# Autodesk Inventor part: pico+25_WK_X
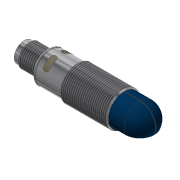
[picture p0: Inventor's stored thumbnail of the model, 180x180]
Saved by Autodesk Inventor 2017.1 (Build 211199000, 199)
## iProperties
Shininess: 20.0
Length Units: 11269
Angle Units: 11279
Time Units: 11290
Mass Units: 11283
Length Display Precision: 2
Angle Display Precision: 2
Part Number: pico+25_WK_X
Material: Nichtrostender Stahl - 440C
Document SubType Name: Modellieren
Description: Ipc-25 /CXX/M18
Checked By: Alves
Created: 2005-08
Designer: Ohle
Manufacturer: Standard
Standards Organization: Custom
Appearance: Aluminium - poliert
Density: 0.0
Volumn: 0.0
Area: 0.0
PropertySet Name: Model Information
Control State: 0
Master: False
Checked Out: False
BESTELLNUMMER: Ipc-25 /CXX/M18
ME: ST
Title: Ipc Sensoren
Author: Ohle
Comments: keine Bemerkung
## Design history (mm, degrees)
sketch "Skizze10"
  geometry: L1 (-43.018, 0)-(17.482, 0); L2 (-39.018, 6.5)-(-39.018, 7.25); L3 (-45.9, 8)-(-45.9, 8); L4 (-23.268, 9)-(0.232, 9); L5 (1.482, 0)-(-82.2, 0); L6 (-24.018, 8.25)-(-23.268, 9); L7 (0.982, 8.25)-(0.232, 9); L8 (-50.518, 6)-(-39.518, 6); L9 (-37.418, 8.25)-(-24.018, 8.25); L10 (-51.018, 4.5)-(-43.018, 4.5); L11 (-43.018, 0)-(-43.018, 4.5); L12 (-37.518, 8.25)-(-38.018, 8.25); L13 (-39.518, 6)-(-39.018, 6.5); L14 (-51.018, 5.5)-(-51.018, 4.5); L15 (-51.018, 5.5)-(-50.518, 6); L16 (-37.518, 8.25)-(-37.518, 8.15); L17 (-37.518, 8.15)-(-37.418, 8.15); L18 (-37.418, 8.15)-(-37.418, 8.25); L19 (0.982, 8.25)-(9.232, 8.25); L20 (17.482, 0)-(17.482, 0); A1 r 1 centre (-38.018, 7.25) between (-38.018, 8.25) and (-39.018, 7.25); A2 r 8.25 centre (9.232, 0) between (17.482, 0) and (9.232, 8.25); 4 further points
  constraints: 41 end point, 8 point on line, 5 parallel, 4 perpendicular, 4 point on circle, 4 tangent, 2 centre point, 2 horizontal, 1 collinear
  dimensions: "d171" = 4.5 distance between parallel lines of L10 L1; "d250" = 0.75 distance from line of L7.start L4; "d256" = 45 deg angle of L4 L6; "d257" = 8.25 distance between parallel lines of L5 L9; "d263" = 8.25 distance between parallel lines of L5 L12; "d266" = 12 distance from line of L2 L14.start; "d269" = 6 distance between parallel lines of L5 L8; "d289" = 135 deg angle of L7 L4; "d290" = 0.5 horizontal distance of L8.end L2.start; "d291" = 45 deg angle of L13 L8 (derived); "d293" = 0.5 horizontal distance of L14.start L8.start; "d294" = 45 deg angle of L15 L8 (derived); "d295" = 8 distance of L10.start L10.end; "d296" = 1.5 distance of L12.start point (-39.018, 8.25); "d297" = 0.1 distance of L16.end L17.end; "d298" = 8.15 distance between parallel lines of L17 L1; "d299" = 15 distance from line of L6.start L2; "d300" = 1 radius of A1; "d338" = 8.25 radius of A2; "d339" = 16.5 horizontal distance of L20.end L7.start; "d340" = 8.25 distance between parallel lines of L1 L19 (derived); "d365" = 25 distance of L7.start L6.start
revolve "Grundkörper pico+" sketch "Skizze10" stored, may be unused: angle "d168" = 90 deg
feature "Gewinde M12" dims "d174" = 10, "d175" = 0
feature "Gewinde M 18" dims "d179" = 10, "d180" = 0
workplane "Arbeitsebene1"
workplane "Arbeitsebene2"
sketch "Skizze13"
  geometry: L1 (-3.409, -3.409)-(3.61, 3.61); L2 (-3.439, 3.439)-(4.105, -4.105); L3 (-12.6, 0)-(12.6, 0) reference; C1 r 0.5 at (2.121, -2.121); C2 r 0.5 at (2.121, 2.121); C3 r 0.5 at (-2.121, 2.121); C4 r 0.5 at (-2.121, -2.121); C5 r 4.5 at (0, 0) reference; C6 r 0.5 at (0, 0); A1 r 3 centre (0, 0) between (-2.121, 2.121) and (2.121, 2.121); 2 further points
  constraints: 6 centre point, 6 point on line, 4 coincident, 4 end point, 4 equal radius, 4 point on circle, 1 horizontal alignment, 1 perpendicular
  dimensions: "d208" = 1 diameter of C3; "d209" = 6 diameter of A1
extrude "Pole" join sketch "Skizze13" distance "d212" = 7; taper "d213" = 0 deg
fillet "Rundung Pole" dims "d214" = 0.5
sketch "Skizze14"
  geometry: C1 r 0.5 at (0, -4.5); A1 r 4.5 centre (0, 0) between (4.435, -0.762) and (4.435, 0.762); A2 r 4.5 centre (0, 0) between (0, 4.5) and (0.499, 4.472) reference; A3 r 0.5 centre (0, 4.5) between (-0.499, 4.472) and (0.499, 4.472); 3 further points
  constraints: 9 point on circle, 3 centre point, 3 coincident, 1 horizontal alignment, 1 vertical alignment
  dimensions: "d215" = 9 diameter of A1; "d280" = 1 diameter of A3; "d330" = 1 diameter of C1
extrude "Verdrehsicherung" join sketch "Skizze14" distance "d217" = 7; taper "d218" = 0 deg
sketch "Skizze18"
  geometry: C1 r 7.25 at (0, 0) reference; C2 r 1 at (-8.15, 0)
  constraints: 1 centre point, 1 horizontal alignment
  dimensions: "d328" = 2 diameter of C2; "d329" = 8.15 distance of C1.centre C2.centre
extrude "Bohrung Ausrichtung" cut sketch "Skizze18" distance "d316" = 0.75; taper "d317" = 0 deg
workplane "Arbeitsebene4"
sketch "Skizze19"
  geometry: L1 (-39.018, 0)-(-30.18, 0); L2 (-34.718, -7.5)-(-34.718, -3); L3 (-31.718, -7.5)-(-31.718, -3); L4 (-31.718, 3)-(-31.718, 7.5); L5 (-34.718, 3)-(-34.718, 7.5); A1 r 1.5 centre (-33.218, 3) between (-31.718, 3) and (-34.718, 3); A2 r 1.5 centre (-33.218, -3) between (-34.718, -3) and (-31.718, -3); A3 r 1.5 centre (-33.218, 7.5) between (-31.718, 7.5) and (-34.718, 7.5); A4 r 1.5 centre (-33.218, -7.5) between (-34.718, -7.5) and (-31.718, -7.5); 4 further points; 1 other entity
  constraints: 10 end point, 8 point on circle, 8 tangent, 4 centre point, 3 equal radius, 2 vertical alignment, 1 horizontal, 2 other
  dimensions: "d319" = 3 diameter of A2; "d320" = 6 distance of A2.centre A1.centre; "d321" = 4.5 distance of A1.centre A3.centre; "d322" = 4.5 distance of A4.centre A2.centre; "d323" = 3 distance from line of A2.centre L1; "d324" = 5.8 dimension on A1.centre; "d325" = 5.8 dimension on A2.centre
feature "Prägen LED-Fenster" sketch "Skizze19" dims "d326" = 0.01, "d327" = 0
workplane "Arbeitsebene5"
sketch "Skizze20"
  geometry: L1 (9.232, -8.25)-(9.232, 8.25) reference; L2 (0.982, -8.25)-(0.982, 8.25) reference; L3 (9.232, -8.25)-(9.232, 8.25) reference; L4 (1.482, -8.25)-(18.508, -8.25); L5 (18.508, -8.25)-(18.508, 8.25); L6 (18.508, 8.25)-(1.482, 8.25); L7 (1.482, 8.25)-(1.482, -8.25)
  constraints: 8 end point, 2 parallel, 1 horizontal, 1 perpendicular
  dimensions: "d342" = 0.5 distance between parallel lines of L7 L2
extrude "USW-Fläche Winkelkopf" cut sketch "Skizze20" distance "d343" = 4.8; taper "d344" = 0 deg
sketch "Skizze21"
  geometry: C1 r 7 at (-9.232, 0); A1 r 7.494 centre (-9.232, 0) between (-9.232, 7.494) and (-9.232, -7.494) reference
  constraints: 1 centre point, 1 coincident
  dimensions: "d345" = 14 diameter of C1
extrude "Extrusion6" cut sketch "Skizze21" distance "d346" = 0.01; taper "d347" = 0 deg
sketch "Skizze22"
  geometry: C1 r 7 at (0, 0) reference; C2 r 4 at (0, 0)
  constraints: 1 centre point, 1 coincident
  dimensions: "d348" = 8 diameter of C2
extrude "Extrusion7" join sketch "Skizze22" distance "d349" = 0.01; taper "d350" = 0 deg
sketch "Skizze28"
  geometry: L1 (-0.982, 8.25)-(-9.232, 8.25) reference; L2 (-0.982, 8.25)-(-0.982, -8.25) reference; L3 (-9.232, -3.45)-(-16.726, -3.45) reference; L4 (-9.232, 8.15)-(-0.982, 8.15); A1 r 8.25 centre (-9.232, 0) between (-9.232, 8.25) and (-16.726, -3.45) reference; A2 r 8.15 centre (-9.232, 0) between (-9.232, 8.15) and (-16.616, -3.45)
  constraints: 2 end point, 2 point on circle, 2 point on line, 1 centre point, 1 coincident, 1 perpendicular, 1 tangent
  dimensions: "d362" = 0.1 radial gap between concentric circles of A2 A1
extrude "Extrusion8" cut sketch "Skizze28" stored distance "d363" = 0.3; taper "d364" = 0 deg
feature "Verdickung1" dims "d366" = 0.1, "d367" = 0.1
sketch "Skizze29"
  geometry: C1 r 5.5 at (0, 0); C2 r 4.5 at (0, 0); C3 r 4.15 at (0, 0); C4 r 5.25 at (0, 0); 2 further points
  constraints: 4 centre point
  dimensions: "d368" = 8.3 diameter of C3; "d369" = 10.5 diameter of C4
extrude "Extrusion9" join sketch "Skizze29" stored distance "d370" = 1; taper "d371" = 0 deg
sketch "Skizze30"
  geometry: C1 r 5.25 at (0, 0) reference; C2 r 7.996 at (0, 0); 1 further point
  constraints: 1 centre point
extrude "Extrusion10" cut sketch "Skizze30" distance "d372" = 2.5; taper "d373" = 0 deg
chamfer "Fase2" distance "d374" = 0.75; stored, may be unused: second distance "d375" = 2, angle "d376" = 30 deg
node "Volumenkörper1"
node "Volumenkörper"
node "Flächenkörper"
node "Projizierte Kontur2"
node "Projizierte Kontur3"
other parameters: "d10" = 14, "d73" = -35, "d130" = 0.2, "d207" = -95.5, "d318" = 8.25, "d341" = -8.25
